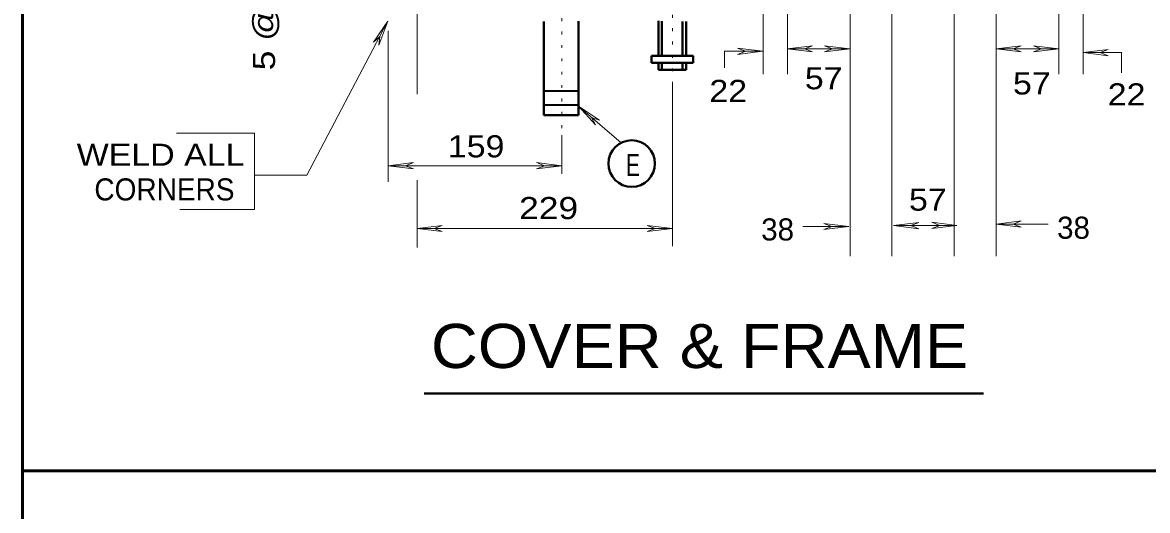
# Model space of a CAD drawing. Extents: x 312583 to 312854, y 144419 to 144597.
# Drawn here: x 312675.44 to 312714.2, y 144526.08 to 144542.88 of the extents above; entities that cross this region are included whole.
import ezdxf
from ezdxf.enums import TextEntityAlignment as Align

# ---------------------------------------------------------------- set-up
doc = ezdxf.new("R2010")
doc.units = 0
doc.header["$LTSCALE"] = 0.3
doc.linetypes.add('DOTTED', pattern=[1.5, 0.3, -1.2])
doc.layers.add('1', color=7, linetype='Continuous', lineweight=40)
doc.layers.add('2', color=7, linetype='Continuous', lineweight=13)

msp = doc.modelspace()

# ---------------------------------------------------------------- linework, layer by layer
at = {"layer": '1', "lineweight": 53}
for p, q in [((312675.4374, 144585.0846), (312675.4374, 144521.3091)), ((312742.1369, 144527.439), (312675.4374, 144527.439))]:
    msp.add_line(p, q, dxfattribs=at)
at = {"layer": '1', "linetype": 'DOTTED', "lineweight": 13}
msp.add_line((312697.8299, 144540.7376), (312697.8299, 144545.4756), dxfattribs=at)
at = {"layer": '1'}
for p, q in [((312693.3985, 144542.9149), (312693.3985, 144539.6873)), ((312694.5945, 144542.9226), (312694.5945, 144539.6873)), ((312697.3469, 144541.7266), (312697.3469, 144542.9379)), ((312697.4695, 144541.7266), (312697.4695, 144542.9226)), ((312698.1825, 144541.7266), (312698.1825, 144542.9149)), ((312698.3052, 144541.7266), (312698.3052, 144542.9149)), ((312697.1092, 144541.7266), (312698.5429, 144541.7266)), ((312697.1092, 144541.4889), (312697.1092, 144541.7266)), ((312698.5429, 144541.4889), (312698.5429, 144541.7266)), ((312697.1092, 144541.4889), (312698.5429, 144541.4889)), ((312697.3469, 144541.2436), (312697.3469, 144541.4889)), ((312697.3469, 144541.2436), (312698.3052, 144541.2436)), ((312697.4695, 144541.2436), (312697.4695, 144541.4889)), ((312698.1825, 144541.2436), (312698.1825, 144541.4889)), ((312698.3052, 144541.2436), (312698.3052, 144541.4889)), ((312694.5945, 144539.6873), (312693.3985, 144539.6873))]:
    msp.add_line(p, q, dxfattribs=at)
at = {"layer": '1', "lineweight": 13}
for p, q in [((312699.6239, 144541.8876), (312699.6239, 144541.316)), ((312713.3012, 144541.8416), (312713.3012, 144541.1387))]:
    msp.add_line(p, q, dxfattribs=at)
at = {"layer": '1', "lineweight": 35}
for p, q in [((312693.3985, 144540.5229), (312694.5945, 144540.5229)), ((312693.3985, 144540.0476), (312694.5945, 144540.0476))]:
    msp.add_line(p, q, dxfattribs=at)
at = {"layer": '2'}
for p, q in [((312700.9579, 144554.5836), (312700.9579, 144541.1032)), ((312711.9825, 144554.5836), (312711.9825, 144541.1032)), ((312701.7935, 144550.9573), (312701.7935, 144541.1032)), ((312703.9555, 144550.9266), (312703.9555, 144534.8343)), ((312705.3892, 144551.0109), (312705.3892, 144534.8343)), ((312707.5435, 144551.0109), (312707.5435, 144537.8319)), ((312708.9849, 144550.9266), (312708.9849, 144534.8343)), ((312711.1392, 144551.0109), (312711.1392, 144541.1032)), ((312689.0362, 144543.5896), (312689.0362, 144540.4079)), ((312685.2332, 144537.6254), (312687.9935, 144542.8689)), ((312688.0242, 144542.9226), (312687.5259, 144542.2019)), ((312688.0242, 144542.9226), (312687.7175, 144542.1023)), ((312687.5259, 144542.2019), (312687.7482, 144542.3936)), ((312687.7175, 144542.1023), (312687.7482, 144542.3936)), ((312688.0395, 144542.5929), (312688.0395, 144537.3949)), ((312700.0762, 144541.9949), (312700.3522, 144541.8876)), ((312700.9425, 144541.8876), (312700.0762, 144541.9949)), ((312701.7859, 144541.9719), (312702.6522, 144542.0793)), ((312701.7859, 144541.9719), (312703.9402, 144541.9719)), ((312701.7859, 144541.9719), (312702.6522, 144541.8646)), ((312702.6522, 144542.0793), (312702.3762, 144541.9719)), ((312702.6522, 144541.8646), (312702.3762, 144541.9719)), ((312703.0739, 144542.0793), (312703.3499, 144541.9719)), ((312703.9402, 144541.9719), (312703.0739, 144542.0793)), ((312703.0739, 144541.8646), (312703.3499, 144541.9719)), ((312703.9402, 144541.9719), (312703.0739, 144541.8646)), ((312708.9849, 144541.9719), (312709.8512, 144542.0793)), ((312708.9849, 144541.9719), (312711.1392, 144541.9719)), ((312708.9849, 144541.9719), (312709.8512, 144541.8646)), ((312709.8512, 144542.0793), (312709.5752, 144541.9719)), ((312709.8512, 144541.8646), (312709.5752, 144541.9719)), ((312710.2729, 144542.0793), (312710.5489, 144541.9719)), ((312711.1392, 144541.9719), (312710.2729, 144542.0793)), ((312710.2729, 144541.8646), (312710.5489, 144541.9719)), ((312711.1392, 144541.9719), (312710.2729, 144541.8646)), ((312711.9825, 144541.8416), (312712.8489, 144541.9489)), ((312712.8489, 144541.9489), (312712.5729, 144541.8416)), ((312699.6239, 144541.8876), (312700.9425, 144541.8876)), ((312700.0762, 144541.7803), (312700.3522, 144541.8876)), ((312700.9425, 144541.8876), (312700.0762, 144541.7803)), ((312711.9825, 144541.8416), (312713.3012, 144541.8416)), ((312711.9825, 144541.8416), (312712.8489, 144541.7343)), ((312712.8489, 144541.7343), (312712.5729, 144541.8416)), ((312697.8299, 144540.7376), (312697.8299, 144535.1793)), ((312696.0665, 144538.7366), (312694.5945, 144539.9939)), ((312694.5945, 144539.9939), (312695.1849, 144539.3499)), ((312694.5945, 144539.9939), (312695.3229, 144539.5109)), ((312695.1849, 144539.3499), (312695.0392, 144539.6106)), ((312695.3229, 144539.5109), (312695.0392, 144539.6106)), ((312680.7461, 144539.0702), (312683.4294, 144539.0702)), ((312683.4294, 144539.0702), (312683.4294, 144536.4406)), ((312694.0195, 144538.9973), (312694.0195, 144537.6709)), ((312688.0395, 144537.9469), (312688.9059, 144538.0543)), ((312688.0395, 144537.9469), (312694.0195, 144537.9469)), ((312688.0395, 144537.9469), (312688.9059, 144537.8396)), ((312688.9059, 144538.0543), (312688.6299, 144537.9469)), ((312688.9059, 144537.8396), (312688.6299, 144537.9469)), ((312693.1532, 144538.0543), (312693.4292, 144537.9469)), ((312694.0195, 144537.9469), (312693.1532, 144538.0543)), ((312693.1532, 144537.8396), (312693.4292, 144537.9469)), ((312694.0195, 144537.9469), (312693.1532, 144537.8396)), ((312707.5435, 144537.8319), (312707.5435, 144534.8343)), ((312683.4294, 144537.6254), (312685.2332, 144537.6254)), ((312689.0362, 144537.4486), (312689.0362, 144535.1256)), ((312680.8611, 144536.4406), (312683.4294, 144536.4406)), ((312689.0362, 144535.7849), (312689.9025, 144535.8923)), ((312689.0362, 144535.7849), (312697.8299, 144535.7849)), ((312689.0362, 144535.7849), (312689.9025, 144535.6776)), ((312689.9025, 144535.8923), (312689.6265, 144535.7849)), ((312689.9025, 144535.6776), (312689.6265, 144535.7849)), ((312696.9635, 144535.8923), (312697.2395, 144535.7849)), ((312697.8299, 144535.7849), (312696.9635, 144535.8923)), ((312696.9635, 144535.6776), (312697.2395, 144535.7849)), ((312697.8299, 144535.7849), (312696.9635, 144535.6776)), ((312702.3225, 144535.8539), (312703.9095, 144535.8539)), ((312703.0432, 144535.9613), (312703.3192, 144535.8539)), ((312703.9095, 144535.8539), (312703.0432, 144535.9613)), ((312703.0432, 144535.7466), (312703.3192, 144535.8539)), ((312703.9095, 144535.8539), (312703.0432, 144535.7466)), ((312705.4505, 144535.8846), (312706.3169, 144535.9919)), ((312705.4505, 144535.8846), (312706.3169, 144535.7773)), ((312705.4812, 144535.8923), (312707.6355, 144535.8923)), ((312706.3169, 144535.9919), (312706.0409, 144535.8846)), ((312706.3169, 144535.7773), (312706.0409, 144535.8846)), ((312706.7692, 144535.9996), (312707.0452, 144535.8923)), ((312707.6355, 144535.8923), (312706.7692, 144535.9996)), ((312706.7692, 144535.7849), (312707.0452, 144535.8923)), ((312707.6355, 144535.8923), (312706.7692, 144535.7849)), ((312708.9849, 144535.9383), (312709.8512, 144536.0456)), ((312708.9849, 144535.9383), (312710.7789, 144535.9383)), ((312708.9849, 144535.9383), (312709.8512, 144535.8309)), ((312709.8512, 144536.0456), (312709.5752, 144535.9383)), ((312709.8512, 144535.8309), (312709.5752, 144535.9383))]:
    msp.add_line(p, q, dxfattribs=at)
at = {"layer": '2', "linetype": 'DOTTED'}
msp.add_line((312694.0195, 144544.8623), (312694.0195, 144538.9973), dxfattribs=at)
at = {"layer": '2', "lineweight": 40}
msp.add_line((312689.2726, 144530.1099), (312708.5492, 144530.1099), dxfattribs=at)
msp.add_circle((312696.4278, 144538.0207), 0.8012, dxfattribs=at)

# ---------------------------------------------------------------- texts
at = {"layer": '2', "width": 1.2}
msp.add_text('5 @ 13 MM TYPICAL', height=0.76, rotation=90, dxfattribs=at).set_placement((312684.1385, 144541.2314))
at = {"layer": '2'}
for s, width, p in [('57 ', 1.15, (312702.3932, 144540.5787)), ('57 ', 1.15, (312709.5641, 144540.3996)), ('22 ', 1.15, (312699.1036, 144540.1431)), ('22 ', 1.15, (312712.8297, 144540.0225)), ('159 ', 1.15, (312690.0922, 144538.2343)), ('WELD ALL ', 1.15, (312677.3049, 144537.9442)), ('E', 0.7, (312696.2352, 144537.5904)), ('CORNERS', 0.95, (312677.9137, 144536.751)), ('57 ', 1.15, (312705.9807, 144536.3986)), ('229 ', 1.2, (312692.5479, 144536.1088))]:
    msp.add_text(s, height=0.76, dxfattribs=dict(at, width=width)).set_placement(p)
for p in [(312700.8902, 144535.3728), (312711.0855, 144535.4322)]:
    msp.add_text('38', height=0.76, dxfattribs=at).set_placement(p)
at = {"layer": '2', "width": 1.1}
msp.add_text('COVER & FRAME', height=1.52, dxfattribs=at).set_placement((312698.7651, 144530.9816), align=Align.CENTER)

doc.saveas('drawing.dxf')
